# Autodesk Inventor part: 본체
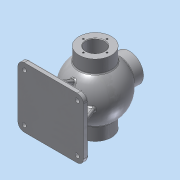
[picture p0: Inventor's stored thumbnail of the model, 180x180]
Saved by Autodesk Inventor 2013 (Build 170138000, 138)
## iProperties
Created: 2018-06
Part Number: 본체
Material: 알루미늄 6061
Document SubType Name: Modeling
Designer: Administrator
Density: 2.71 g/cm^3
Mass: 1509.6 g
Surface Area: 1153.7 cm^2
Volume: 557.047 cm^3
Author: Administrator
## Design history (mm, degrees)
sketch "스케치1"
  geometry: L1 (0, 53)-(0, -53); A1 r 53 centre (0, 0) between (0, 53) and (0, -53); 1 further point
  constraints: 2 end point, 2 point on circle, 1 centre point, 1 coincident, 1 midpoint, 1 vertical
  dimensions: "d0" = 106 diameter of A1
revolve "회전1" sketch "스케치1" stored, may be unused: angle "d1" = 90 deg
node "작업 평면1"
sketch "스케치2"
  geometry: C1 r 31 at (0, 0); 1 further point
  constraints: 1 centre point, 1 coincident
  dimensions: "d3" = 62 diameter of C1
extrude "돌출1" join sketch "스케치2" distance "d5" = 136; taper "d6" = 0 deg
node "작업 평면2"
sketch "스케치3"
  geometry: C1 r 27 at (0, 0); 1 further point
  constraints: 1 centre point, 1 coincident
  dimensions: "d8" = 54 diameter of C1
extrude "돌출2" join sketch "스케치3" stored distance "d9" = 36; taper "d10" = 0 deg
sketch "스케치4"
  geometry: L1 (0, 43)-(0, -43); A1 r 43 centre (0, 0) between (0, 43) and (0, -43); 1 further point
  constraints: 2 end point, 2 point on circle, 1 centre point, 1 coincident, 1 midpoint, 1 vertical
  dimensions: "d11" = 86 diameter of A1
revolve "회전2" sketch "스케치4" stored, may be unused: angle "d13" = 90 deg
sketch "스케치5"
  geometry: C1 r 31 at (0, 0) reference; C2 r 17.5 at (0, 0)
  constraints: 1 centre point, 1 coincident
  dimensions: "d15" = 35 diameter of C2
extrude "돌출3" cut sketch "스케치5" stored distance "d16" = 36; taper "d17" = 0 deg
sketch "스케치6"
  geometry: C1 r 27 at (0, 0) reference; C2 r 13 at (0, 0)
  constraints: 1 centre point, 1 coincident
  dimensions: "d18" = 26 diameter of C2
extrude "돌출4" cut sketch "스케치6" distance "d19" = 65; taper "d20" = 0 deg
node "작업 평면3"
sketch "스케치7"
  geometry: L1 (-62.5, -57.5)-(62.5, -57.5); L2 (62.5, -57.5)-(62.5, 57.5); L3 (62.5, 57.5)-(-62.5, 57.5); L4 (-62.5, 57.5)-(-62.5, -57.5); L5 (-62.5, -57.5)-(62.5, 57.5); L6 (62.5, -57.5)-(-62.5, 57.5); 1 further point
  constraints: 12 end point, 2 midpoint, 2 parallel, 1 horizontal, 1 perpendicular
  dimensions: "d22" = 115 distance of L1.end L2.end; "d24" = 125 distance of L2.end L3.end
extrude "돌출5" join sketch "스케치7" distance "d25" = 10; taper "d26" = 0 deg
fillet "모깎기1" dims "d27" = 12
sketch "스케치10"
  geometry: L1 (-52.5, -75)-(-33.226, -27.295); L2 (50.5, -75)-(-50.5, -75) reference; L3 (-62.5, -75)-(-50.5, -75) reference; L4 (50.5, -75)-(62.5, -75) reference; L5 (33.226, -27.295)-(52.5, -75); L6 (-62.5, -85)-(-62.5, -75) reference; L7 (-52.5, -75)-(52.5, -75); A1 r 43 centre (0, 0) between (-13, 40.988) and (13, 40.988) reference; A2 r 43 centre (0, 0) between (-33.226, -27.295) and (33.226, -27.295); 1 further point
  constraints: 6 end point, 4 point on circle, 2 point on line, 1 centre point, 1 coincident, 1 horizontal alignment, 1 perpendicular
  dimensions: "d35" = 10 distance of L3.start L1.start; "d36" = 10 distance of L4.end L5.end; "d38" = 22 deg angle of L1 L6
extrude "돌출7" join sketch "스케치10" stored distance "d39" = 8; taper "d40" = 0 deg
sketch "스케치11"
  geometry: L1 (-75, 47.5)-(-56.798, 40.146); L2 (-75, 57.5)-(-85, 57.5) reference; L3 (-75, 57.5)-(-75, 45.5) reference; 1 further point
  constraints: 2 end point, 1 point on line
  dimensions: "d41" = 10 distance from line of L1.start L2; "d42" = 22 deg angle of L1 L2
feature "리브1" sketch "스케치11" dims "d43" = 1, "d44" = 8, "d45" = 0, "d46" = 0, "d47" = 1, "d48" = 1
sketch "스케치12"
  geometry: L1 (0, -50.25)-(18.5, -50.25); L2 (18.5, -50.25)-(18.5, -52); L3 (18.5, -52)-(0, -52); L4 (0, -51.125)-(18.5, -52); L5 (18.5, -50.25)-(-18.5, -52); L6 (-31, -68)-(31, -68) reference; L7 (0, -50.25)-(0, -52); 3 further points
  constraints: 12 end point, 4 midpoint, 2 perpendicular, 2 vertical alignment, 1 horizontal, 1 parallel, 1 point on line
  dimensions: "d50" = 16 distance from line of L6 L2.end; "d51" = 1.75 distance between parallel lines of L3 L1; "d53" = 37 diameter of L2 L7
revolve "회전3" sketch "스케치12" stored, may be unused: angle "d54" = 90 deg
sketch "스케치13"
  geometry: C1 r 31 at (0, 0) reference; 1 further point
  constraints: 1 vertical alignment
  dimensions: "d55" = 24 distance of C1.centre point (0, 24)
hole "구멍1" sketch "스케치13" at (0, 24) diameter "d56" = 3.242; stored, may be unused: countersink angle "d60" = 90 deg, drill point angle "d62" = 118 deg; dims "d57" = 16, "d58" = 4, "d59" = 2, "d61" = 19
sketch "스케치15"
  geometry: C1 r 17.5 at (0, 0) reference; 1 further point
  constraints: 1 vertical alignment
  dimensions: "d66" = 22.5 distance of C1.centre point (0, 22.5)
hole "구멍2" sketch "스케치15" at (0, 22.5) diameter "d67" = 3.242; stored, may be unused: countersink angle "d71" = 90 deg, drill point angle "d73" = 118 deg; dims "d68" = 12, "d69" = 4, "d70" = 2, "d72" = 15
sketch "스케치16"
  geometry: C1 r 27 at (0, 0) reference; 1 further point
  constraints: 1 vertical alignment
  dimensions: "d74" = 20 distance of C1.centre point (0, 20)
hole "구멍3" sketch "스케치16" at (0, 20) diameter "d75" = 3.242; stored, may be unused: countersink angle "d79" = 90 deg, drill point angle "d81" = 118 deg; dims "d76" = 9, "d77" = 4, "d78" = 2, "d80" = 11
fillet "모깎기2" dims "d85" = 3
fillet "모깎기3" dims "d86" = 3
fillet "모깎기4" dims "d87" = 3
chamfer "모따기1" distance "d88" = 1; stored, may be unused: second distance "d89" = 2, angle "d90" = 45 deg
sketch "스케치17"
  geometry: A1 r 9 centre (50.5, -45.5) between (50.5, -54.5) and (59.5, -45.5) reference; A2 r 9 centre (50.5, 45.5) between (59.5, 45.5) and (50.5, 54.5) reference; A3 r 9 centre (-50.5, 45.5) between (-50.5, 54.5) and (-59.5, 45.5) reference; A4 r 9 centre (-50.5, -45.5) between (-59.5, -45.5) and (-50.5, -54.5) reference; 5 further points
  constraints: 4 coincident
hole "구멍4" sketch "스케치17" at (-50.5, 45.5), (-50.5, -45.5), (50.5, -45.5), (50.5, 45.5) diameter "d91" = 8; stored, may be unused: countersink angle "d95" = 90 deg, drill point angle "d97" = 0 deg; dims "d92" = 9, "d93" = 12, "d94" = 3, "d96" = 11
node "작업 평면4"
sketch "스케치18"
  geometry: L1 (0, -27)-(0, 27) reference; 2 further points
  constraints: 1 other
  dimensions: "d98" = 10 distance from line of point (10, 0) L1; "d99" = 27 vertical distance of point (10, 0) L1.start
feature "엠보싱1" sketch "스케치18" dims "d0" = 106, "d100" = 0.5, "d101" = 0
node "솔리드1"
mirror "대칭1"
pattern_circular "원형 패턴1" dims angle "d64" = 360 deg
pattern_circular "원형 패턴2" dims angle "d83" = 360 deg
other parameters: "d2" = 68, "d7" = 65, "d21" = -85
